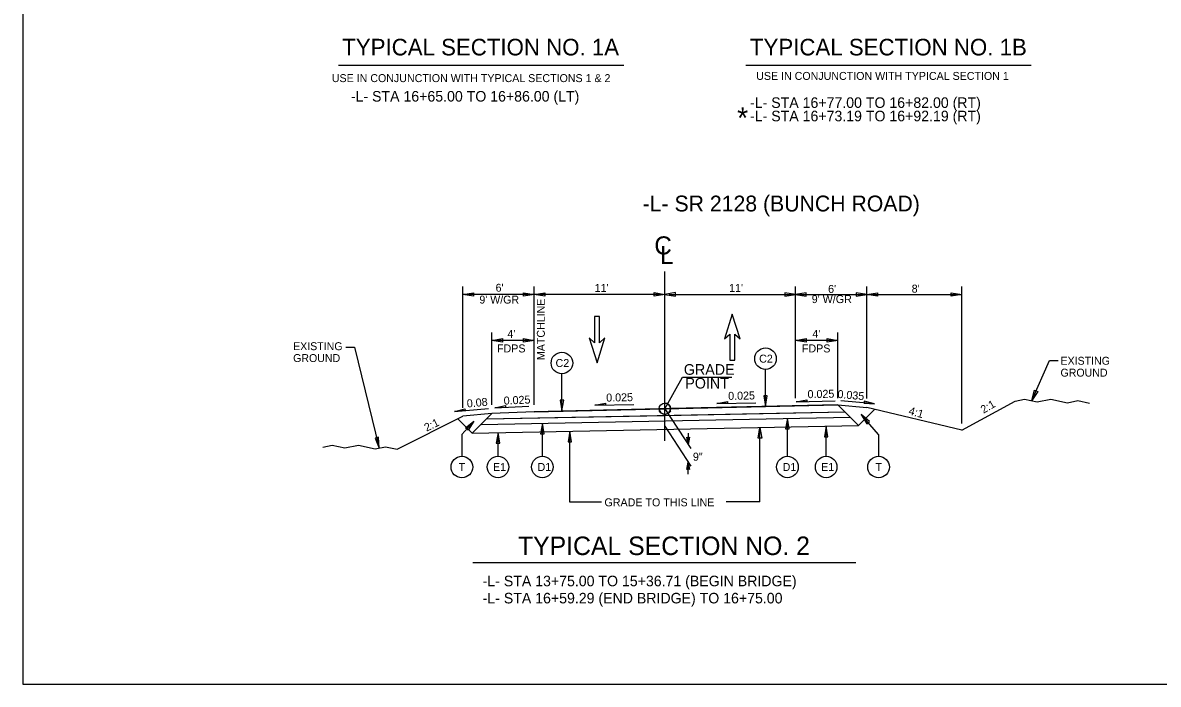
# Model space of a CAD drawing. Extents: x 574442 to 2463611, y -53527 to 675895.
# Drawn here: x 574441.8 to 574537.4, y -53527.1 to -53471.4 of the extents above; entities that cross this region are included whole.
import ezdxf

# ---------------------------------------------------------------- set-up
doc = ezdxf.new("R2010")
doc.units = 0
for name, color, linetype in [('Old_Level_11', 7, 'Continuous'), ('Old_Level_2', 7, 'Continuous'), ('Old_Level_21', 7, 'Continuous'), ('Old_Level_22', 7, 'Continuous'), ('Old_Level_23', 7, 'Continuous'), ('Old_Level_3', 7, 'Continuous'), ('Old_Level_49', 7, 'Continuous'), ('Prop Shade Heavy', 7, 'Continuous'), ('Sheet Plot Border Outside CELL', 7, 'Continuous')]:
    doc.layers.add(name, color=color, linetype=linetype)

msp = doc.modelspace()

# ---------------------------------------------------------------- linework, layer by layer
at = {"layer": 'Old_Level_11'}
for p, q in [((574495.882, -53503.909), (574498.063, -53507.264)), ((574495.867, -53505.373), (574498.063, -53508.749))]:
    msp.add_line(p, q, dxfattribs=at)
for points in [[(574497.949, -53506.298), (574497.842, -53506.923), (574497.73, -53506.294), (574497.842, -53506.374)], [(574497.949, -53506.298), (574497.842, -53506.923), (574497.73, -53506.294), (574497.842, -53506.374)], [(574497.734, -53509.033), (574497.842, -53508.408), (574497.953, -53509.037), (574497.842, -53508.957)]]:
    msp.add_lwpolyline(points, close=True, dxfattribs=at)
for centre in [(574487.215, -53500.057), (574504.348, -53499.688), (574478.793, -53508.818), (574481.836, -53508.814), (574485.567, -53508.814), (574506.192, -53508.814), (574509.452, -53508.814), (574513.862, -53508.818)]:
    msp.add_circle(centre, 0.909, dxfattribs=at)
at = {"layer": 'Old_Level_21'}
for p, q in [((574497.842, -53505.968), (574497.842, -53506.923)), ((574497.842, -53509.409), (574497.842, -53508.408))]:
    msp.add_line(p, q, dxfattribs=at)
at = {"layer": 'Old_Level_22'}
for p, q in [((574469.02, -53498.73), (574469.755, -53498.73)), ((574469.755, -53498.73), (574471.841, -53507.216)), ((574526.764, -53503.226), (574528.25, -53499.839)), ((574528.25, -53499.839), (574528.982, -53499.839)), ((574484.882, -53504.162), (574510.437, -53503.574)), ((574495.424, -53503.959), (574495.384, -53503.919)), ((574495.424, -53503.959), (574495.384, -53503.919)), ((574495.879, -53503.905), (574495.402, -53503.905)), ((574495.879, -53503.905), (574495.879, -53503.427)), ((574496.357, -53503.905), (574495.879, -53503.905)), ((574495.879, -53504.383), (574495.879, -53503.905)), ((574496.339, -53503.959), (574496.379, -53503.919)), ((574496.339, -53503.959), (574496.379, -53503.919)), ((574510.437, -53503.574), (574512.175, -53505.312)), ((574510.437, -53503.574), (574512.882, -53503.814)), ((574512.175, -53505.312), (574513.521, -53503.966)), ((574520.882, -53505.721), (574512.882, -53503.814)), ((574520.882, -53505.721), (574525.363, -53503.273)), ((574473.335, -53507.318), (574478.882, -53504.545)), ((574479.669, -53505.962), (574478.462, -53504.755)), ((574481.326, -53504.305), (574478.882, -53504.545)), ((574481.326, -53504.305), (574479.669, -53505.962)), ((574480.405, -53505.225), (574511.467, -53504.604)), ((574480.866, -53504.765), (574511.025, -53504.162)), ((574484.882, -53504.162), (574481.326, -53504.305)), ((574495.424, -53504.172), (574495.384, -53504.132)), ((574495.424, -53504.172), (574495.384, -53504.132)), ((574496.339, -53504.172), (574496.379, -53504.132)), ((574496.339, -53504.172), (574496.379, -53504.132)), ((574479.669, -53505.962), (574512.175, -53505.312))]:
    msp.add_line(p, q, dxfattribs=at)
for points in [[(574525.363, -53503.273), (574526.146, -53503.102), (574527.213, -53503.316), (574528.372, -53503.102), (574529.774, -53503.407), (574530.628, -53503.224), (574531.603, -53503.438)], [(574467.094, -53507.154), (574467.878, -53506.983), (574468.945, -53507.196), (574470.103, -53506.983), (574471.505, -53507.288), (574472.359, -53507.105), (574473.335, -53507.318)]]:
    msp.add_lwpolyline(points, dxfattribs=at)
msp.add_circle((574495.879, -53503.905), 0.478, dxfattribs=at)
for start, end in [(180, 270), (0, 90)]:
    msp.add_arc((574495.879, -53503.905), 0.478, start, end, dxfattribs=at)
at = {"layer": 'Old_Level_23'}
for p, q in [((574495.882, -53506.607), (574495.882, -53492.357)), ((574478.882, -53503.826), (574478.882, -53493.613)), ((574487.882, -53494.283), (574478.882, -53494.283)), ((574484.882, -53503.592), (574484.882, -53493.613)), ((574486.548, -53494.283), (574486.548, -53494.283)), ((574495.525, -53494.283), (574487.882, -53494.283)), ((574496.238, -53494.283), (574503.882, -53494.283)), ((574503.882, -53494.283), (574509.215, -53494.283)), ((574505.215, -53494.283), (574505.215, -53494.283)), ((574506.882, -53503.025), (574506.882, -53493.613)), ((574509.215, -53494.283), (574520.882, -53494.283)), ((574512.882, -53503.053), (574512.882, -53493.613)), ((574520.882, -53505.163), (574520.882, -53493.613)), ((574481.326, -53503.592), (574481.326, -53497.477)), ((574483.446, -53498.155), (574481.326, -53498.155)), ((574484.882, -53498.155), (574482.92, -53498.155)), ((574510.437, -53498.155), (574506.882, -53498.155)), ((574510.437, -53503.025), (574510.437, -53497.477)), ((574487.215, -53504.082), (574487.215, -53500.966)), ((574504.348, -53503.714), (574504.348, -53500.597)), ((574495.884, -53503.905), (574497.365, -53501.247)), ((574497.365, -53501.247), (574501.507, -53501.247)), ((574478.178, -53504.133), (574481.031, -53503.877)), ((574481.566, -53503.832), (574484.428, -53503.701)), ((574489.99, -53503.609), (574493.26, -53503.544)), ((574500.254, -53503.463), (574503.524, -53503.398)), ((574506.935, -53503.318), (574510.205, -53503.253)), ((574513.529, -53503.504), (574510.676, -53503.249)), ((574506.192, -53507.905), (574506.192, -53504.71)), ((574513.862, -53506.088), (574512.388, -53504.391)), ((574478.793, -53506.088), (574479.545, -53505.222)), ((574481.836, -53507.905), (574481.836, -53505.909)), ((574485.567, -53507.905), (574485.567, -53505.122)), ((574487.882, -53511.789), (574487.882, -53505.798)), ((574503.882, -53511.747), (574503.882, -53505.478)), ((574509.452, -53507.905), (574509.452, -53505.366)), ((574478.793, -53506.088), (574478.793, -53507.909)), ((574513.862, -53506.088), (574513.862, -53507.909)), ((574490.538, -53511.789), (574487.882, -53511.789)), ((574503.882, -53511.747), (574501.023, -53511.747))]:
    msp.add_line(p, q, dxfattribs=at)
for points in [[(574478.882, -53494.283), (574479.777, -53494.133), (574479.777, -53494.432)], [(574484.882, -53494.283), (574483.986, -53494.432), (574483.986, -53494.133)], [(574484.882, -53494.283), (574485.777, -53494.133), (574485.777, -53494.432)], [(574495.882, -53494.276), (574494.986, -53494.425), (574494.986, -53494.126)], [(574495.882, -53494.276), (574496.777, -53494.425), (574496.777, -53494.126)], [(574506.882, -53494.283), (574505.986, -53494.133), (574505.986, -53494.432)], [(574506.882, -53494.283), (574507.777, -53494.432), (574507.777, -53494.133)], [(574512.882, -53494.283), (574511.986, -53494.133), (574511.986, -53494.432)], [(574512.882, -53494.283), (574513.777, -53494.134), (574513.777, -53494.432)], [(574520.882, -53494.283), (574519.986, -53494.432), (574519.986, -53494.134)], [(574481.326, -53498.155), (574482.222, -53498.005), (574482.222, -53498.304)], [(574484.882, -53498.155), (574483.986, -53498.304), (574483.986, -53498.005)], [(574506.882, -53498.155), (574507.777, -53498.005), (574507.777, -53498.304)], [(574510.437, -53498.155), (574509.542, -53498.304), (574509.542, -53498.005)], [(574504.348, -53503.714), (574504.497, -53502.818), (574504.199, -53502.818)], [(574526.764, -53503.226), (574526.986, -53502.345), (574527.259, -53502.465)], [(574478.178, -53504.133), (574479.056, -53503.904), (574479.07, -53504.053)], [(574481.566, -53503.832), (574482.454, -53503.642), (574482.461, -53503.791)], [(574487.215, -53504.082), (574487.364, -53503.187), (574487.066, -53503.187)], [(574489.99, -53503.609), (574490.883, -53503.441), (574490.886, -53503.591)], [(574500.254, -53503.463), (574501.146, -53503.296), (574501.149, -53503.446)], [(574506.935, -53503.318), (574507.827, -53503.151), (574507.83, -53503.3)], [(574513.529, -53503.504), (574512.65, -53503.275), (574512.637, -53503.424)], [(574479.79, -53504.941), (574479.315, -53505.715), (574479.09, -53505.519)], [(574506.192, -53504.71), (574506.043, -53505.605), (574506.342, -53505.605)], [(574512.388, -53504.391), (574512.863, -53505.165), (574513.088, -53504.97)], [(574481.836, -53505.909), (574481.687, -53506.805), (574481.985, -53506.805)], [(574485.567, -53505.122), (574485.418, -53506.018), (574485.716, -53506.018)], [(574487.882, -53505.798), (574487.732, -53506.693), (574488.031, -53506.693)], [(574503.882, -53505.478), (574504.031, -53506.373), (574503.732, -53506.373)], [(574509.452, -53505.366), (574509.303, -53506.262), (574509.601, -53506.262)], [(574471.841, -53507.216), (574471.776, -53506.31), (574471.485, -53506.381)]]:
    msp.add_lwpolyline(points, close=True, dxfattribs=at)
at = {"layer": 'Old_Level_3'}
for p, q in [((574492.432, -53474.99), (574468.405, -53474.99)), ((574526.707, -53474.99), (574502.681, -53474.99)), ((574479.726, -53516.859), (574511.957, -53516.859))]:
    msp.add_line(p, q, dxfattribs=at)
at = {"layer": 'Old_Level_49'}
for points in [[(574490.822, -53497.931), (574490.375, -53498.344), (574490.375, -53496.143), (574489.963, -53496.143), (574489.963, -53498.344), (574489.516, -53497.931), (574490.169, -53500.028)], [(574500.895, -53498.026), (574501.341, -53497.614), (574501.341, -53499.814), (574501.754, -53499.814), (574501.754, -53497.614), (574502.201, -53498.026), (574501.548, -53495.929)]]:
    msp.add_lwpolyline(points, close=True, dxfattribs=at)
at = {"layer": 'Prop Shade Heavy'}
for p, q in [((574495.402, -53503.92), (574484.882, -53504.162)), ((574496.379, -53503.919), (574496.355, -53503.943)), ((574510.437, -53503.574), (574496.378, -53503.898)), ((574511.025, -53504.162), (574510.437, -53503.574)), ((574481.326, -53504.305), (574480.866, -53504.765)), ((574480.866, -53504.765), (574495.881, -53504.465)), ((574484.882, -53504.162), (574481.326, -53504.305)), ((574495.881, -53504.465), (574511.025, -53504.162))]:
    msp.add_line(p, q, dxfattribs=at)
for points in [[(574496.378, -53503.898), (574496.379, -53503.919)], [(574495.879, -53504.382), (574495.879, -53504.382), (574495.881, -53504.465)], [(574495.881, -53504.465), (574495.879, -53504.382)]]:
    msp.add_lwpolyline(points, dxfattribs=at)
for start, end in [(181.84196, 270), (270, 355.41837)]:
    msp.add_arc((574495.879, -53503.905), 0.478, start, end, dxfattribs=at)
at = {"layer": 'Sheet Plot Border Outside CELL'}
msp.add_lwpolyline([(574441.833, -53527.117), (574628.889, -53527.117), (574628.889, -53404.895), (574441.833, -53404.895)], close=True, dxfattribs=at)

# ---------------------------------------------------------------- texts
at = {"layer": 'Old_Level_2'}
for s, p in [('GRADE', (574497.476, -53501.048)), ('POINT', (574497.597, -53502.206))]:
    msp.add_text(s, height=0.8978, dxfattribs=at).set_placement(p)
at = {"layer": 'Old_Level_21'}
for s, height, p in [("6'", 0.6667, (574481.632, -53494.049)), ("11'", 0.6733, (574489.969, -53494.069)), ("11'", 0.6733, (574501.284, -53494.069)), ("6'", 0.6733, (574509.616, -53494.156)), ("8'", 0.6733, (574516.649, -53494.13)), ("9' W/GR", 0.6667, (574480.267, -53495.049)), ("9' W/GR", 0.6733, (574508.238, -53495.009)), ("4'", 0.6733, (574482.626, -53497.936)), ("4'", 0.6733, (574508.289, -53497.935)), ('EXISTING', 0.6667, (574464.591, -53498.973)), ('FDPS', 0.6733, (574481.746, -53499.165)), ('FDPS', 0.6733, (574507.409, -53499.164)), ('GROUND', 0.6667, (574464.591, -53499.973)), ('C2', 0.6733, (574486.677, -53500.393)), ('C2', 0.6733, (574503.81, -53500.025)), ('EXISTING', 0.6667, (574529.174, -53500.201)), ('GROUND', 0.6667, (574529.174, -53501.201)), ('9"', 0.6733, (574498.238, -53508.283)), ('T', 0.673, (574478.528, -53509.154)), ('E1', 0.6733, (574481.412, -53509.15)), ('D1', 0.6733, (574485.164, -53509.15)), ('D1', 0.6733, (574505.789, -53509.15)), ('E1', 0.6733, (574509.028, -53509.15)), ('T', 0.673, (574513.597, -53509.154)), ('GRADE TO THIS LINE', 0.67333, (574490.792, -53512.128)), ('-L- STA 13+75.00 TO 15+36.71 (BEGIN BRIDGE)', 0.88889, (574480.54, -53518.859)), ('-L- STA 16+59.29 (END BRIDGE) TO 16+75.00', 0.88889, (574480.54, -53520.303))]:
    msp.add_text(s, height=height, dxfattribs=at).set_placement(p)
for s, height, rotation, p in [('0.08', 0.6733, 5.13358, (574479.239, -53503.805)), ('0.025', 0.6733, 2.63199, (574482.328, -53503.565)), ('0.025', 0.6733, 1.14576, (574490.947, -53503.309)), ('0.025', 0.6733, 1.14576, (574501.211, -53503.164)), ('0.025', 0.6733, 1.14576, (574507.892, -53503.018)), ('0.035', 0.6733, 354.89111, (574510.382, -53502.99)), ('4:1', 0.6733, 344.39866, (574516.341, -53504.375)), ('2:1', 0.6667, 30.34985, (574522.694, -53504.332)), ('2:1', 0.6733, 26.03624, (574475.827, -53505.843))]:
    msp.add_text(s, height=height, rotation=rotation, dxfattribs=at).set_placement(p)
at = {"layer": 'Old_Level_23'}
for s, p in [('USE IN CONJUNCTION WITH TYPICAL SECTIONS 1 & 2', (574467.85, -53476.396)), ('USE IN CONJUNCTION WITH TYPICAL SECTION 1', (574503.566, -53476.21))]:
    msp.add_text(s, height=0.67, dxfattribs=at).set_placement(p)
msp.add_text('MATCHLINE', height=0.67, rotation=90, dxfattribs=at).set_placement((574485.775, -53499.809))
at = {"layer": 'Old_Level_3'}
for s, height, p in [('TYPICAL SECTION NO. 1A', 1.39972, (574468.724, -53474.15)), ('TYPICAL SECTION NO. 1B', 1.39972, (574503.038, -53474.15)), ('-L- STA 16+65.00 TO 16+86.00 (LT)', 0.88889, (574469.452, -53478.035)), ('-L- STA 16+77.00 TO 16+82.00 (RT)', 0.88889, (574503.047, -53478.569)), ('*', 1.778, (574501.961, -53480.298)), ('-L- STA 16+73.19 TO 16+92.19 (RT)', 0.88889, (574503.047, -53479.696)), ('-L- SR 2128 (BUNCH ROAD)', 1.33598, (574494.008, -53487.291)), ('C', 1.521, (574494.991, -53490.911)), ('L', 1.521, (574495.468, -53491.724)), ('TYPICAL SECTION NO. 2', 1.55993, (574483.514, -53516.232))]:
    msp.add_text(s, height=height, dxfattribs=at).set_placement(p)

doc.saveas('drawing.dxf')
